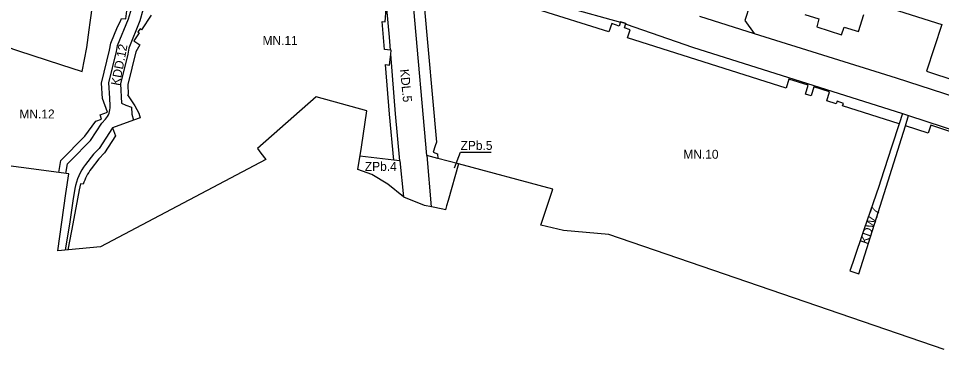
# Model space of a CAD drawing. Extents: x 7416797 to 7419013, y 5549660 to 5551534.
# Drawn here: x 7417362 to 7417878, y 5550095 to 5550280 of the extents above; entities that cross this region are included whole.
import ezdxf

# ---------------------------------------------------------------- set-up
doc = ezdxf.new("R2010")
doc.units = 0
for name, color, linetype in [('LIN_Linia Zabudowy Nieprzekraczalna', 7, 'Continuous'), ('LIN_linie_rozgraniczajace', 7, 'Continuous'), ('TXT_Oznaczenia_przeznaczen', 7, 'Continuous')]:
    doc.layers.add(name, color=color, linetype=linetype)

msp = doc.modelspace()

# ---------------------------------------------------------------- linework, layer by layer
at = {"layer": 'LIN_Linia Zabudowy Nieprzekraczalna'}
for p, q in [((7417416.64, 5550214.06), (7417410.5, 5550204.57)), ((7417410.5, 5550204.57), (7417407.3, 5550201.24)), ((7417407.3, 5550201.24), (7417402.97, 5550195.69))]:
    msp.add_line(p, q, dxfattribs=at)
for points in [[(7417854.6, 5550220.88), (7417822.96, 5550230.87), (7417823.46, 5550232.28), (7417820.04, 5550233.5), (7417819.51, 5550231.96), (7417814.23, 5550233.64), (7417815.79, 5550238.78), (7417806.98, 5550241.49), (7417805.41, 5550236.43), (7417802.25, 5550237.43), (7417803.81, 5550242.42), (7417793.06, 5550245.76), (7417791.56, 5550240.82), (7417702.82, 5550268.88), (7417704.32, 5550273.38), (7417701.09, 5550274.47), (7417701.9, 5550276.88), (7417698.86, 5550277.88), (7417698.06, 5550275.48), (7417696.12, 5550276.14), (7417693.96, 5550276.86), (7417692.43, 5550272.17), (7417611.45, 5550297.78)], [(7417384.85, 5550193.71), (7417385.97, 5550200.41), (7417399.43, 5550213.95), (7417405.52, 5550222.38), (7417408.76, 5550223.52), (7417407.92, 5550225.94), (7417412, 5550227.36), (7417409.33, 5550235.1), (7417408.73, 5550243.61), (7417413.28, 5550262.1), (7417413.92, 5550265.97), (7417417.6, 5550275.05), (7417419.43, 5550278.3), (7417419.84, 5550279.79), (7417422.43, 5550279.53), (7417423.01, 5550285.46)], [(7417572.18, 5550200.56), (7417569.76, 5550226.24), (7417567.54, 5550253.95), (7417569.78, 5550253.72), (7417570.42, 5550259.85), (7417570.64, 5550261.97), (7417570.24, 5550262.01), (7417566.86, 5550262.36), (7417565.59, 5550278.06), (7417567.25, 5550277.89), (7417567.95, 5550285.32)], [(7417589.15, 5550286.98), (7417595.98, 5550210.57), (7417595.31, 5550208.58), (7417594.1, 5550204.98), (7417596.55, 5550204.14), (7417596.78, 5550201.53)], [(7417840.12, 5550288.54), (7417878.46, 5550276.31), (7417869.88, 5550250.33), (7417951.32, 5550223.45)], [(7417436.59, 5550281.54), (7417431.12, 5550273.42), (7417430.26, 5550274), (7417429.06, 5550272.2), (7417429.82, 5550271.69), (7417426.89, 5550267.25), (7417430.19, 5550265), (7417427.96, 5550261.14), (7417423.4, 5550242.9), (7417423.71, 5550237.19), (7417423.36, 5550236.97), (7417427.37, 5550230.83), (7417429.59, 5550226.87), (7417430.38, 5550224.3), (7417426.61, 5550222.94), (7417414.87, 5550218.71), (7417416.64, 5550214.06)], [(7417801.84, 5550282), (7417809.66, 5550279.48), (7417808.55, 5550275.13), (7417822.46, 5550270.66), (7417823.89, 5550274.9), (7417831.83, 5550272.37), (7417834.9, 5550282.03)], [(7418202.86, 5550107.48), (7418088.49, 5550144.72), (7418038.24, 5550161.14), (7418031.79, 5550163.31), (7417989.56, 5550177), (7417990.47, 5550179.64), (7417987.45, 5550180.72), (7417986.89, 5550179.22), (7417985.65, 5550179.68), (7417985.14, 5550178.4), (7417983.81, 5550178.86), (7417983.97, 5550179.27), (7417981.48, 5550180.23), (7417981.26, 5550179.68), (7417950.32, 5550189.71), (7417913.08, 5550202.54), (7417904.24, 5550205.44), (7417895.44, 5550208.37), (7417888.52, 5550210.72), (7417889.7, 5550214.55), (7417881.87, 5550216.96), (7417872.29, 5550220.12), (7417870.86, 5550215.59), (7417858.1, 5550219.74)], [(7417402.97, 5550195.69), (7417402.25, 5550194.72), (7417401.57, 5550193.71), (7417400.94, 5550192.67), (7417400.36, 5550191.59), (7417399.82, 5550190.5), (7417399.34, 5550189.38), (7417398.92, 5550188.24), (7417398.55, 5550187.08)], [(7417398.55, 5550187.08), (7417396.97, 5550187.32), (7417396.19, 5550183.89), (7417394.46, 5550173.98), (7417391.88, 5550161.04), (7417389.84, 5550150.44)]]:
    msp.add_lwpolyline(points, dxfattribs=at)
at = {"layer": 'LIN_linie_rozgraniczajace'}
for p, q in [((7417431.88, 5550284.37), (7417430.12, 5550278.34)), ((7417743.12, 5550281.1), (7417773.52, 5550271.33)), ((7417430.12, 5550278.34), (7417424.1, 5550263.17)), ((7417423.5, 5550259.73), (7417419.37, 5550243.29)), ((7417424.1, 5550263.17), (7417423.5, 5550259.73)), ((7417419.37, 5550243.29), (7417419.97, 5550232.41)), ((7417419.97, 5550232.41), (7417422.28, 5550231.26)), ((7417422.28, 5550231.26), (7417425.47, 5550230.15)), ((7417426.61, 5550222.94), (7417414.87, 5550218.71)), ((7417404.27, 5550203.86), (7417399.82, 5550198.15)), ((7417590.61, 5550203.18), (7417593.03, 5550174.47)), ((7417575.59, 5550200.16), (7417577.48, 5550180.04)), ((7417393.89, 5550184.65), (7417392.75, 5550177.82)), ((7417392.75, 5550177.82), (7417391.09, 5550166.05)), ((7417391.09, 5550166.05), (7417388.5, 5550150.32))]:
    msp.add_line(p, q, dxfattribs=at)
for points in [[(7417873.74, 5550605.53), (7417863.34, 5550573.52), (7417854.43, 5550546.09), (7417846.81, 5550520.04), (7417845.27, 5550514.42), (7417843.62, 5550510.36), (7417824.36, 5550451.41), (7417823.69, 5550449.9), (7417823.43, 5550448.8), (7417802.63, 5550384.88), (7417799.31, 5550374.64), (7417780.6, 5550316.7), (7417780.05, 5550314.74), (7417779.59, 5550313.09), (7417768.36, 5550278.62), (7417773.52, 5550271.33)], [(7417336.94, 5550270.27), (7417348.08, 5550266.58), (7417355.33, 5550263.98), (7417362.32, 5550261.63), (7417385.88, 5550253.92), (7417397.94, 5550250.05), (7417400.58, 5550263.54), (7417401.84, 5550273.38), (7417402.48, 5550277.5), (7417403.1, 5550282.66), (7417404.5, 5550295.46), (7417404.9, 5550299.68), (7417405.3, 5550310), (7417405.5, 5550314.62), (7417406.24, 5550325.37), (7417406.27, 5550328.97), (7417406.52, 5550333.54), (7417406.79, 5550337.31), (7417407.4, 5550350.15), (7417407.79, 5550358), (7417408.02, 5550362.03), (7417408.15, 5550364.55), (7417408.17, 5550365.02), (7417408.78, 5550369.31)], [(7417584.39, 5550300.76), (7417592.45, 5550308.74), (7417614.79, 5550303.02), (7417669.2, 5550285.81), (7417698.81, 5550277.72), (7417698.86, 5550277.88), (7417701.9, 5550276.88), (7417701.83, 5550276.67), (7417702.02, 5550276.6), (7417739.04, 5550263.72), (7417856.45, 5550226.59)], [(7417575.59, 5550200.16), (7417573.1, 5550226.53), (7417570.42, 5550259.85), (7417570.64, 5550261.97), (7417570.24, 5550262.01), (7417569.66, 5550269.32), (7417568.17, 5550285.28), (7417567.33, 5550292.47), (7417566.65, 5550297.38), (7417565.34, 5550305.12)], [(7417590.61, 5550203.18), (7417583.29, 5550285.09), (7417584.39, 5550300.76)], [(7417388.81, 5550193.18), (7417389.7, 5550198.5), (7417391.6, 5550200.41), (7417402.67, 5550211.61), (7417408.91, 5550221.18), (7417410.98, 5550223.46), (7417411.59, 5550224.21), (7417412.14, 5550225.03), (7417412.61, 5550225.9), (7417412.99, 5550226.82), (7417413.28, 5550227.78), (7417413.47, 5550228.75), (7417413.56, 5550229.73), (7417413.56, 5550230.7), (7417413.55, 5550230.86), (7417413.33, 5550235.21), (7417412.88, 5550243.75), (7417417.21, 5550261.25), (7417417.76, 5550264.66), (7417423.74, 5550279.56), (7417425.42, 5550285.12)], [(7417773.52, 5550271.33), (7417853.01, 5550246.64), (7417932.88, 5550220.63), (7417933.29, 5550221.97), (7417933.89, 5550223.94), (7417945.13, 5550220.23), (7417944.62, 5550218.54), (7417969.99, 5550210.96), (7417975.48, 5550206.76), (7417998.7, 5550199.2)], [(7417879.77, 5550094.76), (7417692.43, 5550159.1), (7417667.07, 5550161.33), (7417654.39, 5550164.23), (7417661.06, 5550184.39), (7417661.06, 5550184.39), (7417608.34, 5550198.45), (7417602.48, 5550178.11), (7417601.59, 5550175.01), (7417600.98, 5550172.88), (7417599.6, 5550173.15), (7417593.18, 5550174.44), (7417589.33, 5550175.22), (7417577.67, 5550179.89), (7417577.48, 5550180.04), (7417568.82, 5550187.09), (7417559.79, 5550192.62), (7417552.08, 5550195.31), (7417553.99, 5550207.78), (7417557.11, 5550228.17), (7417528.81, 5550235.86), (7417495.89, 5550206.99), (7417497.85, 5550204.46), (7417500.56, 5550200.96), (7417408.09, 5550152.06), (7417384.31, 5550149.95), (7417384.31, 5550149.95), (7417388.8, 5550182), (7417390.48, 5550192.96), (7417390.48, 5550192.96), (7417336.94, 5550200.05)], [(7417425.47, 5550230.15), (7417425.61, 5550226.2), (7417426.61, 5550222.94)], [(7417856.45, 5550226.59), (7417854.6, 5550220.88), (7417850.51, 5550208.31), (7417846.25, 5550195.17), (7417844.4, 5550189.47), (7417843.24, 5550185.88), (7417835.17, 5550162.18), (7417828.69, 5550143.41), (7417827.05, 5550138.65), (7417832.07, 5550137.1), (7417834.42, 5550144.17), (7417858.1, 5550219.74), (7417859.9, 5550225.47)], [(7417856.45, 5550226.59), (7417859.9, 5550225.47)], [(7417859.9, 5550225.47), (7417917.95, 5550206.56)], [(7417414.87, 5550218.71), (7417407.35, 5550207.07), (7417404.27, 5550203.86)], [(7417575.59, 5550200.16), (7417572.18, 5550200.56), (7417553.23, 5550202.81)], [(7417608.34, 5550198.45), (7417596.78, 5550201.53), (7417590.61, 5550203.18)], [(7417399.82, 5550198.15), (7417398.73, 5550196.66), (7417397.72, 5550195.09), (7417396.82, 5550193.46), (7417396.01, 5550191.77), (7417395.31, 5550190.04), (7417394.73, 5550188.26), (7417394.25, 5550186.47), (7417393.89, 5550184.65)]]:
    msp.add_lwpolyline(points, dxfattribs=at)
at = {"layer": 'TXT_Oznaczenia_przeznaczen'}
msp.add_lwpolyline([(7417606.09, 5550196.24), (7417609.46, 5550205.04), (7417626.48, 5550205.04)], dxfattribs=at)

# ---------------------------------------------------------------- texts
for s, p in [('MN.11', (7417498.75, 5550264.94)), ('MN.12', (7417362.85, 5550223.84)), ('ZPb.5', (7417609.46, 5550206.29)), ('MN.10', (7417733.97, 5550201.34)), ('ZPb.4', (7417555.95, 5550194.58))]:
    msp.add_text(s, height=5, dxfattribs=at).set_placement(p)
for s, rotation, p in [('KDD.12', 78.9971, (7417418.87, 5550241.89)), ('KDL.5', 275.3927, (7417575.64, 5550251.21)), ('KDW.7', 70.6426, (7417837.14, 5550153.15))]:
    msp.add_text(s, height=5, rotation=rotation, dxfattribs=at).set_placement(p)

doc.saveas('drawing.dxf')
